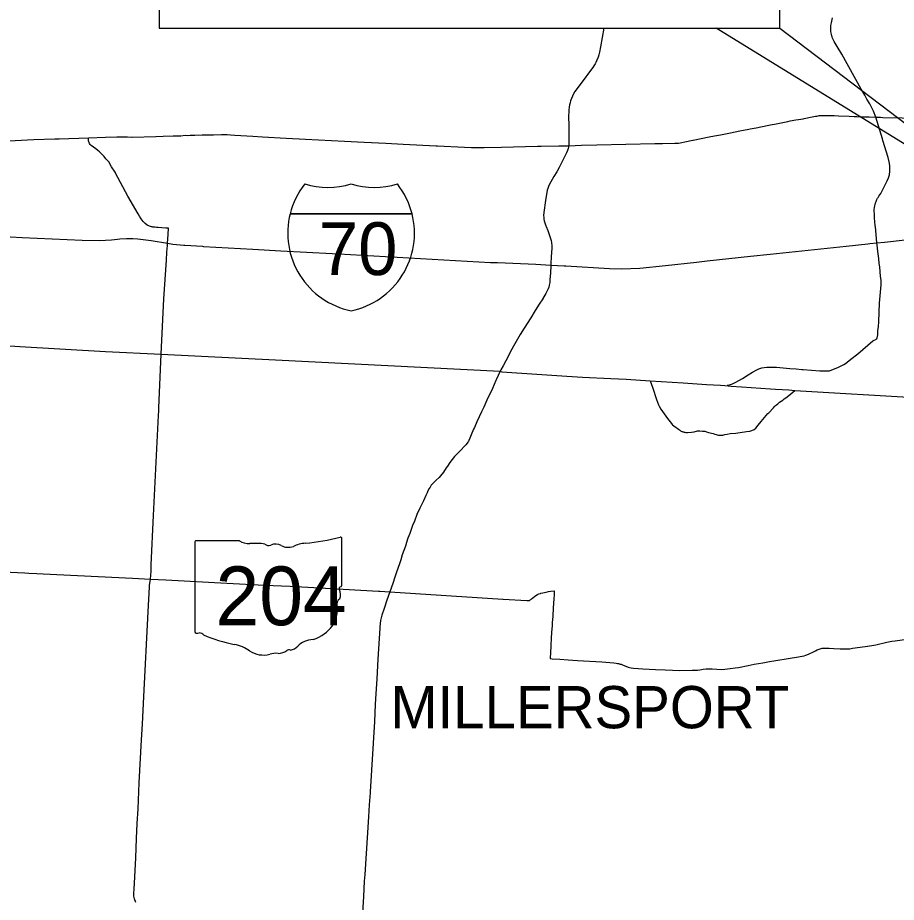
# Model space of a CAD drawing. Extents: x 1761803 to 2441803, y 509895 to 949895.
# Drawn here: x 1933337 to 1974924, y 772284 to 814167 of the extents above; entities that cross this region are included whole.
import ezdxf

# ---------------------------------------------------------------- set-up
doc = ezdxf.new("R2010")
doc.units = 0
for name, color, linetype in [('GM_X_County', 7, 'Continuous'), ('GM_X_County_Road', 7, 'Continuous'), ('GM_X_Minor_Lake', 7, 'Continuous'), ('GM_X_Minor_River', 7, 'Continuous'), ('GM_X_Minor_River_Text', 7, 'Continuous'), ('GM_X_State_Location', 7, 'Continuous'), ('GM_X_Township_Road', 7, 'Continuous'), ('GM_X_Unincorporated_Location', 7, 'Continuous')]:
    doc.layers.add(name, color=color, linetype=linetype)

msp = doc.modelspace()

# ---------------------------------------------------------------- linework, layer by layer
at = {"layer": 'GM_X_County'}
msp.add_lwpolyline([(1926704, 799049), (1933445, 798603), (1937496, 798356), (1940133, 798233), (1945542, 797971), (1956177, 797424), (1956246, 797400), (1959326, 797192), (1960069, 797146), (1961405, 797089), (1962142, 797048), (1963274, 796972), (1964839, 796877), (1965938, 796805), (1966607, 796763), (1966808, 796758), (1967105, 796727), (1967603, 796692), (1968964, 796601), (1969207, 796585), (1969838, 796543), (1970120, 796524), (1976043, 796175), (1978896, 798059)], dxfattribs=at)
at = {"layer": 'GM_X_Minor_Lake'}
for points in [[(1971826, 813538), (1971823, 813595), (1971820, 813657), (1971822, 813712), (1971829, 813777), (1971832, 813804)], [(1971832, 813804), (1971839, 813855), (1971851, 813928), (1971911, 814167)], [(1961085, 813677), (1960916, 812791), (1960868, 812539), (1960837, 812411), (1960805, 812299), (1960746, 812149), (1960695, 812044), (1960666, 811978), (1960613, 811888), (1960557, 811803), (1960502, 811728), (1960011, 811072), (1959896, 810923), (1959771, 810750), (1959713, 810667), (1959648, 810557), (1959597, 810455), (1959548, 810340), (1959508, 810236), (1959480, 810129), (1959457, 810035), (1959438, 809934), (1959424, 809805), (1959416, 809677), (1959414, 809554), (1959416, 809001), (1959421, 808469), (1959424, 808106)], [(1972344, 812442), (1972344, 812442), (1972130, 812801), (1972037, 812955), (1971988, 813042), (1971943, 813130), (1971911, 813199), (1971890, 813254), (1971870, 813309), (1971855, 813369), (1971840, 813442), (1971826, 813536), (1971826, 813538)], [(1973949, 809458), (1973949, 809458), (1973841, 809749), (1973668, 810095), (1973534, 810316), (1973439, 810492), (1973264, 810777), (1972344, 812442)], [(1974620, 806901), (1974625, 807040), (1974622, 807172), (1974593, 807336), (1974536, 807552), (1974286, 808360), (1974267, 808429), (1973949, 809458)], [(1937973, 806800), (1937943, 806857), (1937778, 807107), (1937643, 807342), (1937513, 807481), (1937424, 807591), (1937330, 807695), (1937204, 807814), (1937128, 807880), (1937041, 807956), (1936816, 808110), (1936762, 808162), (1936731, 808209), (1936712, 808255), (1936702, 808287), (1936695, 808331), (1936694, 808378), (1936692, 808483)], [(1959424, 808106), (1959413, 808032), (1959399, 807968), (1959366, 807880), (1959317, 807770), (1959065, 807256), (1958972, 807079), (1958857, 806873), (1958719, 806653), (1958633, 806507), (1958568, 806391), (1958499, 806252), (1958461, 806170), (1958429, 806086), (1958401, 805999), (1958320, 805517), (1958242, 804947), (1958230, 804801), (1958235, 804702), (1958242, 804629), (1958262, 804543), (1958338, 804314), (1958350, 804283)], [(1939110, 804765), (1939041, 804879), (1938553, 805723), (1937973, 806800)], [(1973936, 805394), (1973964, 805472), (1973985, 805519), (1974003, 805558), (1974035, 805616), (1974062, 805658), (1974096, 805711), (1974189, 805851), (1974435, 806321), (1974495, 806444), (1974555, 806586), (1974598, 806732), (1974620, 806893), (1974620, 806901)], [(1973895, 804645), (1973889, 804708), (1973887, 804901), (1973880, 804997), (1973882, 805088), (1973890, 805188), (1973904, 805267), (1973916, 805320), (1973936, 805394)], [(1940476, 804205), (1940356, 804210), (1940167, 804219), (1939987, 804231), (1939899, 804237), (1939829, 804243), (1939783, 804246), (1939741, 804254), (1939694, 804263), (1939664, 804270), (1939568, 804299), (1939460, 804348), (1939365, 804423), (1939272, 804521), (1939182, 804645), (1939110, 804765)], [(1973905, 804545), (1973895, 804645)], [(1940422, 803389), (1940429, 803499), (1940454, 803906), (1940476, 804205)], [(1958350, 804283), (1958427, 804085), (1958544, 803762), (1958587, 803624), (1958607, 803531), (1958611, 803476)], [(1974017, 803394), (1974004, 803503), (1973968, 803895), (1973932, 804266), (1973929, 804294), (1973905, 804545)], [(1940375, 802681), (1940401, 803058), (1940422, 803389)], [(1958611, 803476), (1958615, 803418), (1958616, 803258), (1958587, 802838), (1958571, 802528)], [(1974119, 802524), (1974090, 802760), (1974051, 803099), (1974049, 803121), (1974017, 803394)], [(1940252, 800850), (1940375, 802681)], [(1958571, 802528), (1958567, 802451), (1958550, 802063), (1958541, 801952), (1958528, 801738), (1958518, 801623), (1958498, 801500), (1958475, 801415), (1958444, 801323), (1958405, 801235), (1958334, 801112), (1958192, 800871), (1958187, 800864)], [(1974182, 801917), (1974138, 802367), (1974119, 802524)], [(1973955, 798934), (1973968, 798939), (1974001, 798964), (1974016, 799015), (1974042, 799150), (1974056, 799336), (1974075, 799553), (1974093, 799764), (1974110, 800218), (1974128, 800653), (1974200, 801517), (1974208, 801707)], [(1974208, 801707), (1974210, 801745), (1974182, 801917)], [(1940131, 798206), (1940133, 798233), (1940252, 800850)], [(1958187, 800864), (1958022, 800604), (1957834, 800298), (1957622, 799962), (1957306, 799460), (1957124, 799168), (1956872, 798731), (1956668, 798363), (1956564, 798164)], [(1970460, 797515), (1970512, 797511), (1971311, 797449), (1971712, 797444), (1971758, 797450), (1971793, 797463), (1971997, 797544), (1972181, 797626), (1972380, 797719), (1972439, 797749), (1972523, 797801), (1972585, 797847), (1972604, 797861), (1972768, 798001), (1973106, 798260), (1973818, 798868), (1973849, 798886), (1973883, 798905), (1973955, 798934)], [(1939662, 788265), (1939770, 790597), (1940002, 795325), (1940015, 795561), (1940023, 795702), (1940133, 798233), (1940131, 798206)], [(1956564, 798164), (1956313, 797685), (1956212, 797492), (1956177, 797424)], [(1966925, 796769), (1966950, 796771), (1967075, 796800), (1967171, 796829), (1967336, 796916), (1967639, 797088), (1967915, 797263), (1968110, 797386), (1968315, 797499), (1968413, 797541), (1968561, 797582), (1968677, 797608), (1968789, 797621), (1968870, 797628), (1969012, 797626), (1969251, 797614), (1969884, 797562), (1970180, 797537), (1970460, 797515)], [(1956177, 797424), (1955985, 797017), (1955973, 796991)], [(1955973, 796991), (1955804, 796616), (1955646, 796279), (1955595, 796167), (1955397, 795727), (1955286, 795507), (1955069, 795027), (1954951, 794771), (1954913, 794686), (1954801, 794413), (1954741, 794260), (1954692, 794148), (1954667, 794103), (1954640, 794065), (1954605, 794017), (1954543, 793940), (1954489, 793878), (1954306, 793690), (1954062, 793446), (1954017, 793398), (1953895, 793245), (1953788, 793100), (1953673, 792941), (1953618, 792859), (1953485, 792652), (1953356, 792477), (1953289, 792403), (1953145, 792269), (1953005, 792130), (1952914, 792027), (1952856, 791940), (1952813, 791873), (1952756, 791765), (1952715, 791672), (1952655, 791546), (1952538, 791293), (1952371, 790939), (1952236, 790649), (1952111, 790336), (1952031, 790128), (1951963, 789935), (1951896, 789750), (1951810, 789519), (1951737, 789315), (1951686, 789147), (1951609, 788934), (1951540, 788729), (1951471, 788504), (1951406, 788316)], [(1963274, 796972), (1963393, 796619), (1963568, 796084), (1963660, 795844), (1963695, 795770), (1963781, 795636), (1963943, 795415), (1964098, 795197), (1964285, 794952), (1964315, 794913), (1964338, 794889), (1964393, 794845), (1964509, 794763), (1964556, 794727), (1964616, 794682), (1964654, 794653), (1964685, 794631), (1964714, 794612), (1964745, 794596), (1964773, 794583), (1964794, 794574), (1964815, 794566), (1964845, 794557), (1964878, 794548), (1964919, 794540), (1964963, 794534), (1965045, 794527), (1965236, 794543), (1965351, 794557), (1965521, 794599), (1965628, 794607), (1965753, 794597), (1965858, 794584), (1965940, 794563), (1966034, 794535), (1966255, 794478), (1966337, 794453), (1966508, 794407), (1966602, 794399), (1966707, 794408), (1966812, 794435), (1966921, 794455), (1967053, 794476), (1967331, 794503), (1967832, 794568), (1967985, 794596), (1968087, 794619), (1968193, 794670), (1968269, 794727), (1968385, 794868), (1968523, 795048), (1968839, 795420), (1968898, 795460), (1969108, 795699), (1969165, 795758), (1969208, 795804), (1969249, 795838), (1969312, 795890), (1969402, 795961), (1969552, 796066), (1969622, 796117), (1969699, 796173), (1969844, 796286), (1970120, 796524)], [(1921174, 788612), (1921784, 788573), (1922832, 788507), (1923267, 788480), (1923569, 788461), (1923801, 788461), (1926597, 788281), (1927949, 788195), (1928747, 788145), (1928972, 788135), (1929900, 788094), (1931066, 788028), (1932642, 787931), (1933679, 787882), (1933866, 787871), (1934236, 787845), (1934539, 787836), (1938763, 787625), (1939615, 787583)], [(1939615, 787583), (1939648, 787966), (1939662, 788265)], [(1951406, 788316), (1951268, 787912), (1951192, 787685), (1951087, 787377)], [(1939577, 787279), (1939615, 787583)], [(1939615, 787583), (1940345, 787545), (1943237, 787396), (1945021, 787303), (1946236, 787245), (1950416, 787011), (1950473, 787008)], [(1938933, 772271), (1938870, 772451), (1938852, 772514), (1938840, 772582), (1938834, 772708), (1938843, 772924), (1938864, 773192), (1938923, 774394), (1938958, 775299), (1938997, 776014), (1939037, 776705), (1939091, 777939), (1939200, 779979), (1939238, 780711), (1939301, 782028), (1939518, 786039), (1939570, 787226), (1939577, 787279)], [(1950473, 787008), (1950945, 786984), (1956307, 786643), (1956319, 786643)], [(1950945, 786984), (1950808, 786582)], [(1951087, 787377), (1951087, 787376), (1950945, 786984)], [(1958265, 786955), (1958353, 786975), (1958465, 786996), (1958569, 787011), (1958735, 787024)], [(1958735, 787024), (1958722, 786796), (1958717, 786699)], [(1950808, 786582), (1950677, 786197), (1950570, 785874), (1950534, 785754), (1950508, 785634), (1950487, 785478), (1950474, 785304)], [(1956319, 786643), (1957429, 786571), (1957478, 786572)], [(1957478, 786572), (1957519, 786573), (1957550, 786576), (1957568, 786581), (1957597, 786600), (1957620, 786617), (1957654, 786647), (1957702, 786690)], [(1957702, 786690), (1957720, 786706), (1957793, 786766), (1957855, 786812), (1957936, 786860), (1958001, 786885), (1958085, 786911), (1958102, 786915), (1958195, 786940), (1958265, 786955)], [(1958717, 786699), (1958714, 786647), (1958689, 786229), (1958661, 785833)], [(1958661, 785833), (1958660, 785821), (1958637, 785528), (1958633, 785455)], [(1958627, 785346), (1958621, 785257), (1958593, 784805)], [(1958633, 785455), (1958627, 785346)], [(1950474, 785304), (1950473, 785289), (1950471, 785268), (1950376, 783796), (1950332, 782859), (1950274, 781919), (1950263, 781647), (1950224, 780837), (1950018, 777517), (1950014, 777466)], [(1972512, 784279), (1972512, 784279), (1972720, 784293), (1972849, 784312), (1973446, 784395), (1973758, 784442), (1973954, 784480), (1974475, 784598), (1974709, 784642), (1974871, 784670), (1975195, 784710), (1976154, 784835), (1977143, 784979), (1977608, 785051), (1977937, 785097)], [(1958589, 784751), (1958576, 784480), (1958573, 784416), (1958536, 783830), (1958632, 783811), (1958995, 783793), (1959388, 783767), (1959835, 783737), (1960991, 783666), (1961550, 783621), (1961669, 783599), (1961735, 783592), (1961784, 783585), (1961808, 783579), (1961856, 783567), (1961900, 783552), (1961962, 783528), (1962237, 783424), (1962301, 783402), (1962370, 783383), (1962485, 783371), (1962927, 783341), (1963230, 783324), (1963529, 783306), (1963983, 783285), (1964681, 783263), (1965255, 783271), (1965378, 783272), (1965506, 783276), (1965630, 783290), (1965787, 783319), (1965918, 783332), (1966213, 783332), (1966657, 783310), (1966802, 783318), (1967062, 783347), (1967289, 783382), (1967450, 783409), (1967908, 783499), (1968203, 783558), (1968607, 783628), (1968922, 783684), (1969121, 783715), (1969893, 783841), (1970193, 783888), (1970473, 783933), (1970570, 783958), (1970643, 783979), (1970760, 784031), (1970837, 784068), (1970968, 784129), (1971101, 784195), (1971184, 784232), (1971327, 784290), (1971369, 784303), (1971416, 784313), (1971460, 784317), (1971554, 784319), (1971739, 784314), (1971974, 784302), (1972269, 784287), (1972512, 784279)], [(1958593, 784805), (1958591, 784775), (1958589, 784751)], [(1950014, 777466), (1949975, 776898)], [(1949975, 776898), (1949936, 776330), (1949766, 773597), (1949742, 773290), (1949704, 772559), (1949416, 767877), (1949411, 767798), (1949262, 765516)]]:
    msp.add_lwpolyline(points, dxfattribs=at)
at = {"layer": 'GM_X_Minor_River'}
for points in [[(1921607, 804533), (1925046, 804265), (1925888, 804213), (1927022, 804147), (1927626, 804112), (1928423, 804064), (1930547, 803979), (1931849, 803860), (1932411, 803824), (1932996, 803790), (1933552, 803763), (1936392, 803629), (1937214, 803614), (1937778, 803653), (1938064, 803686)], [(1938064, 803686), (1938172, 803698), (1938480, 803717), (1938643, 803717), (1938783, 803707), (1939030, 803695), (1939529, 803636), (1939662, 803616), (1940429, 803499), (1940679, 803451), (1941195, 803392), (1941243, 803390), (1942089, 803343)], [(1942089, 803343), (1942139, 803340), (1944468, 803208)], [(1958567, 802451), (1959209, 802419), (1959277, 802416), (1961351, 802290), (1961918, 802270), (1962787, 802311), (1964007, 802429), (1965460, 802596), (1965970, 802649), (1968030, 802872), (1968956, 802972), (1972558, 803352), (1973580, 803459)], [(1973580, 803459), (1973678, 803469), (1974004, 803503)], [(1974004, 803503), (1974365, 803542), (1974514, 803558)], [(1974514, 803558), (1975208, 803633), (1975463, 803661), (1975519, 803667)], [(1944468, 803208), (1945790, 803133), (1948229, 802999), (1948539, 802992), (1955720, 802577), (1956045, 802580), (1957857, 802493), (1958567, 802451)]]:
    msp.add_lwpolyline(points, dxfattribs=at)
at = {"layer": 'GM_X_Minor_River_Text'}
for points in [[(1968815, 809060), (1969046, 809105), (1969155, 809124), (1969400, 809175), (1969786, 809254), (1969899, 809277)], [(1969899, 809277), (1970163, 809331), (1970297, 809344), (1970521, 809385)], [(1970521, 809385), (1970561, 809393), (1970934, 809466), (1971101, 809499), (1971160, 809511), (1971220, 809525), (1971265, 809533), (1971299, 809538), (1971355, 809540), (1971390, 809543), (1971511, 809539), (1971653, 809533), (1971679, 809534)], [(1971679, 809534), (1971814, 809538), (1971828, 809538), (1971975, 809534), (1972182, 809525), (1972693, 809510), (1972932, 809494)], [(1972932, 809494), (1973062, 809485), (1973333, 809479)], [(1973333, 809479), (1973413, 809477), (1973634, 809467), (1973949, 809458), (1974013, 809456)], [(1974013, 809456), (1974171, 809450), (1974280, 809448)], [(1974280, 809448), (1975207, 809425), (1975748, 809402)], [(1965304, 808367), (1966073, 808521), (1966313, 808566), (1966602, 808621), (1967071, 808720), (1967521, 808803), (1967937, 808888)], [(1967937, 808888), (1968003, 808901), (1968297, 808957), (1968812, 809060), (1968815, 809060)], [(1921927, 808035), (1922024, 808039), (1922660, 808052), (1923208, 808064), (1924565, 808089), (1926129, 808124), (1927262, 808156), (1927848, 808169), (1931393, 808309), (1932006, 808305), (1932354, 808317), (1932659, 808328), (1932741, 808330), (1933216, 808345), (1934103, 808406), (1935088, 808430)], [(1935088, 808430), (1935296, 808435), (1936692, 808483)], [(1936692, 808483), (1937498, 808510), (1938028, 808532), (1938063, 808531)], [(1938063, 808531), (1938275, 808527)], [(1938275, 808527), (1938538, 808521)], [(1938538, 808521), (1938745, 808517), (1938750, 808517)], [(1938750, 808517), (1939878, 808549), (1940227, 808558)], [(1940227, 808558), (1940702, 808571)], [(1940702, 808571), (1940868, 808574), (1941053, 808580), (1941264, 808598), (1941394, 808596), (1941499, 808598)], [(1941499, 808598), (1941721, 808601), (1942066, 808614), (1942084, 808614)], [(1942084, 808614), (1942602, 808625), (1942976, 808637), (1943102, 808637), (1943258, 808635), (1943414, 808620)], [(1943414, 808620), (1943615, 808605), (1944461, 808560), (1944928, 808526), (1946047, 808467), (1946960, 808416), (1948197, 808356), (1948811, 808324), (1949733, 808280), (1950766, 808227), (1951583, 808186), (1953139, 808106)], [(1957945, 808082), (1958112, 808086), (1958958, 808107), (1959424, 808106), (1960023, 808127), (1960745, 808142), (1963489, 808205), (1963851, 808212), (1964440, 808227), (1964609, 808232), (1964772, 808256), (1964914, 808287), (1965298, 808366), (1965304, 808367)], [(1953139, 808106), (1953210, 808102), (1954487, 808037), (1954812, 808024), (1955424, 808021), (1956235, 808039), (1957945, 808082)]]:
    msp.add_lwpolyline(points, dxfattribs=at)
at = {"layer": 'GM_X_State_Location'}
for points in [[(1940037, 813677), (1969413, 813677), (1969413, 828511), (1940037, 828511)], [(1982314, 803873), (1966404, 813677), (1969413, 813677)]]:
    msp.add_lwpolyline(points, close=True, dxfattribs=at)
at = {"layer": 'GM_X_Township_Road'}
for p, q in [((1948682, 787296), (1948682, 789507)), ((1941722, 789330), (1941722, 785103)), ((1943829, 789402), (1941790, 789402)), ((1948682, 787297), (1948682, 787296))]:
    msp.add_line(p, q, dxfattribs=at)
for centre, major_axis, start_param, end_param in [((1946203, 795165), (7382, 0), 4.814394, 5.042369), ((1948605, 789516), (77.5, 0), 6.141152, 7.989035), ((1941801, 789339), (80.6, 0), 1.712693, 3.28349), ((1944314, 789893), (782, 0), 4.042523, 4.731795), ((1944573, 787030), (2808, 0), 1.404758, 1.657858), ((1945211, 789361), (226, 0), 3.836095, 5.185415), ((1945542, 788872), (469, 0), 0.950623, 2.079405), ((1946148, 789542), (564, 0), 4.081561, 5.145723), ((1947144, 788111), (1485, 0), 1.699011, 2.107814), ((1948665, 787134), (120, 0), 1.883978, 3.671073), ((1947902, 786854), (720, 0), 5.934695, 6.695948), ((1948600, 787288), (82.9, 0), 5.05454, 6.418171), ((1948960, 786371), (524, 0), 2.387724, 3.262537), ((1946616, 786090), (1846, 0), 5.101752, 6.440018), ((1941802, 785094), (81.4, 0), 3.00124, 4.508301), ((1941814, 785526), (621, 0), 4.665946, 4.897461), ((1941941, 784859), (224, 0), 0.519207, 1.627899), ((1944768, 788657), (5331, 0), 4.195997, 4.488961), ((1943179, 783204), (1668, 0), 0.823519, 1.323587), ((1947395, 783916), (1011, 0), 1.647645, 2.488434), ((1944982, 784838), (1058, 0), 4.026481, 4.996735), ((1945594, 783377), (870, 0), 1.495662, 1.94098), ((1945671, 784522), (564, 0), 4.691044, 5.507374), ((1946181, 784112), (159, 0), 1.147584, 2.315152), ((1946114, 784693), (597, 0), 4.937069, 5.64225)]:
    msp.add_ellipse(centre, major_axis=major_axis, ratio=0.8, start_param=start_param, end_param=end_param, dxfattribs=at)
at = {"layer": 'GM_X_Unincorporated_Location'}
for p, q in [((1946232, 804887), (1952003, 804887)), ((1952003, 804887), (1946232, 804887)), ((1952003, 804887), (1946232, 804887))]:
    msp.add_line(p, q, dxfattribs=at)
for centre, start, end in [((1949867, 803968), 141.669, 165.8066), ((1948022, 809880), 253.0091, 286.9909), ((1950213, 809880), 253.0091, 286.9909), ((1948367, 803968), 14.1934, 38.331), ((1949867, 803968), 165.8066, 258.463), ((1948367, 803968), 281.537, 14.1934)]:
    msp.add_arc(centre, 3750, start, end, dxfattribs=at)

# ---------------------------------------------------------------- texts
at = {"layer": 'GM_X_County_Road'}
msp.add_text('MILLERSPORT', height=2000, rotation=0, dxfattribs=at).set_placement((1950978, 780524))
at = {"layer": 'GM_X_Township_Road'}
msp.add_text('204', height=2784.4, dxfattribs=at).set_placement((1942700, 785401))
at = {"layer": 'GM_X_Unincorporated_Location'}
msp.add_text('70', height=2500, dxfattribs=at).set_placement((1947592, 801981))

doc.saveas('drawing.dxf')
